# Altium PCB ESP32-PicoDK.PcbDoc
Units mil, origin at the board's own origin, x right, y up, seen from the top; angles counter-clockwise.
Board outline 2080 x 860 mil, 2 copper layers (Top1, Bottom2), stack 40.202 mil thick; 41 components, 60 nets, 226 pads, 128 vias.
Unrouted connection lines stored in the file: 56.
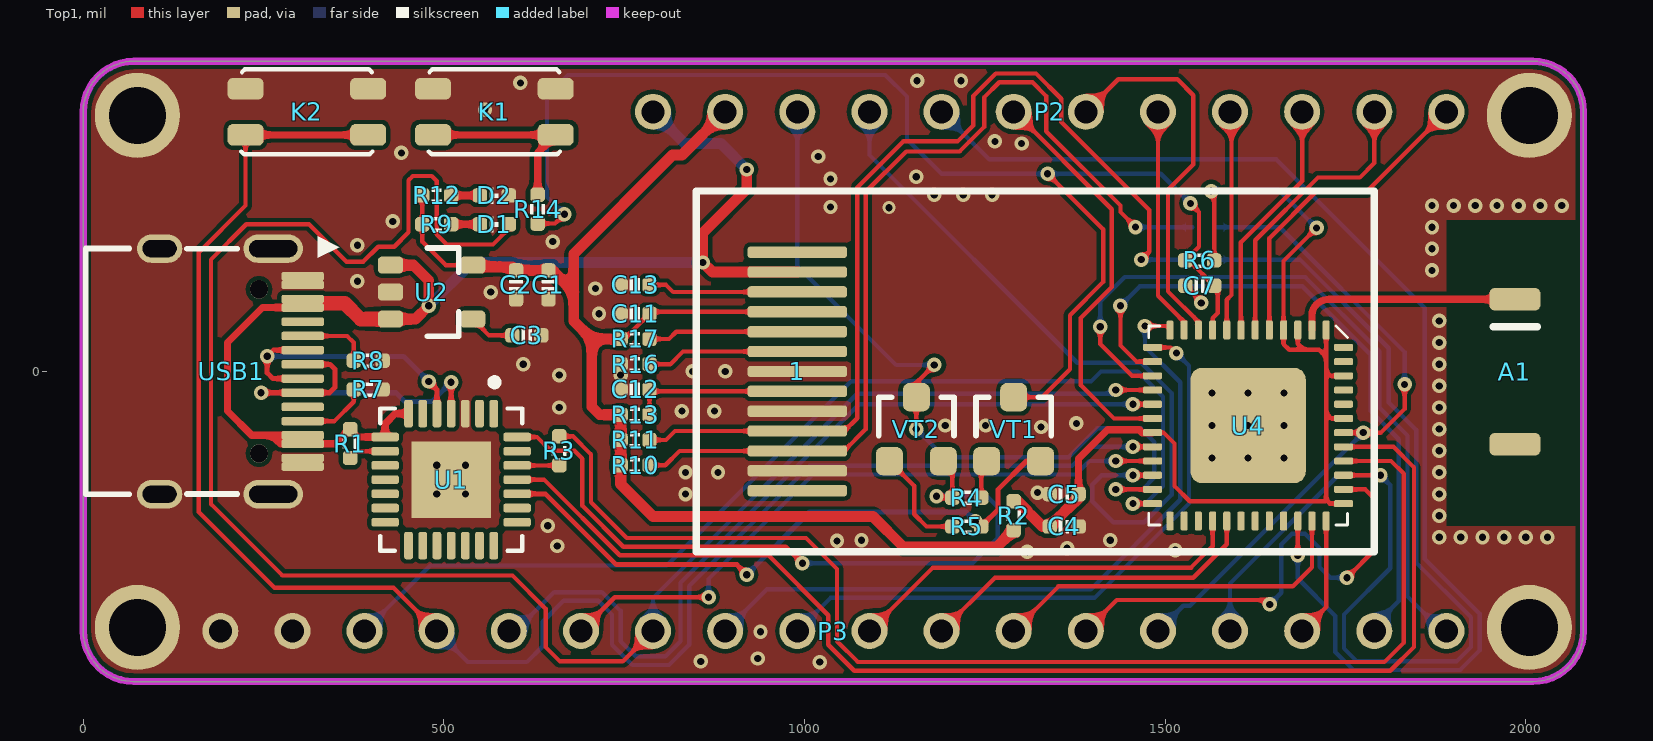
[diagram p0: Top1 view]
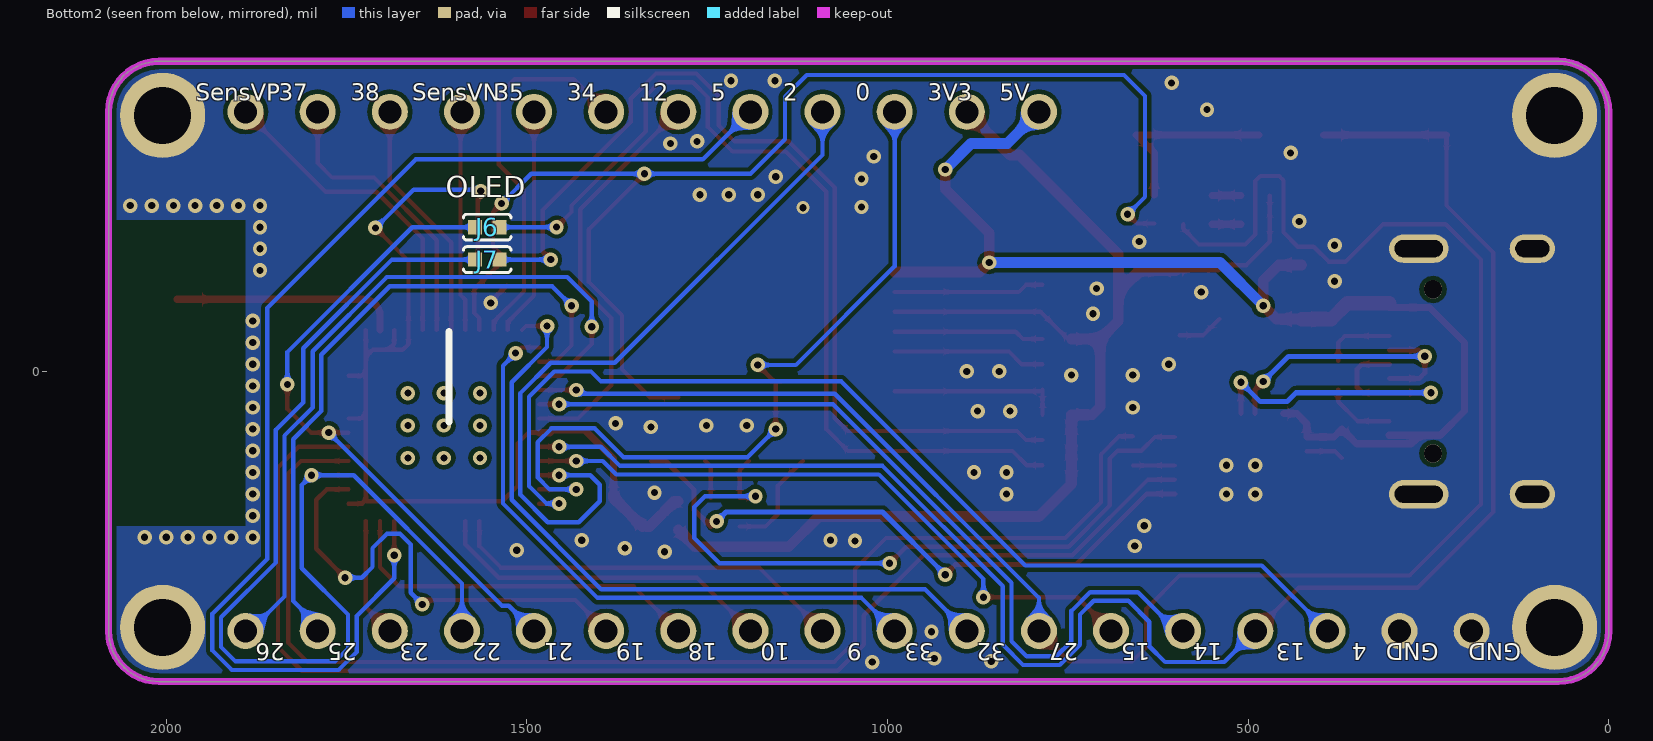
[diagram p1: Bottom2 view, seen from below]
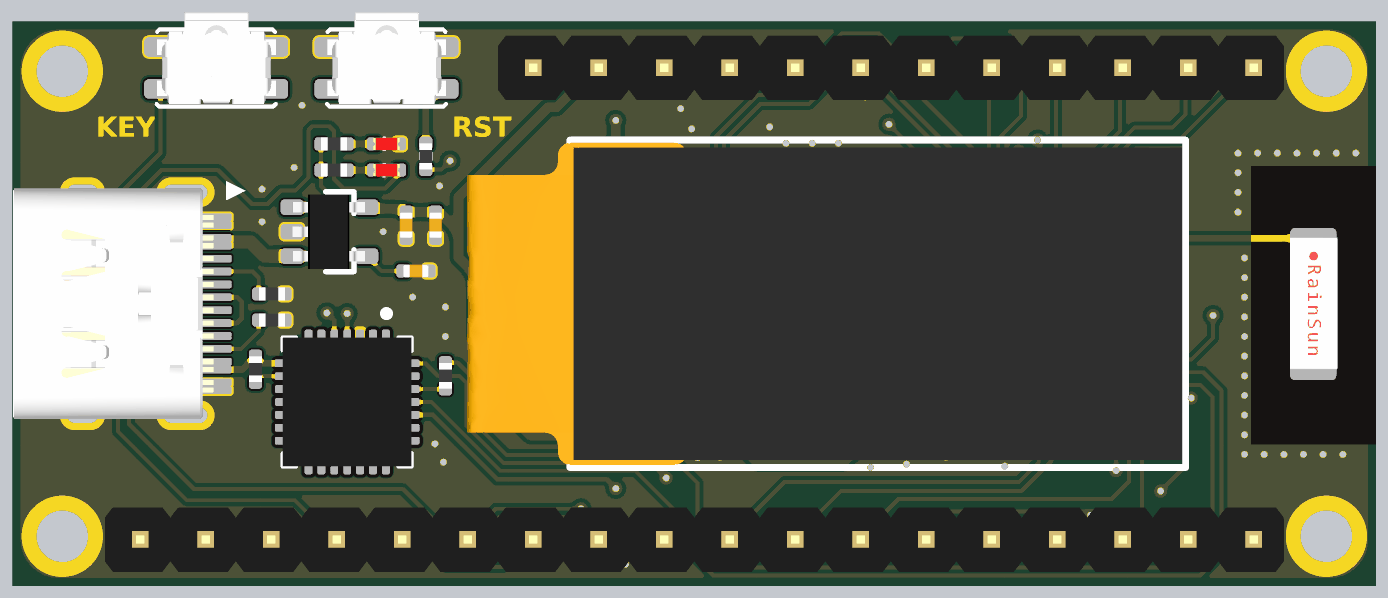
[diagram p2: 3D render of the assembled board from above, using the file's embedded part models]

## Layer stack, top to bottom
Top Solder: solder mask 0.4, Solder Resist, Dk 3.5
Top1: signal copper 1.4
Dielectric 1: core 37.4016, FR-4, Dk 4.2
Bottom2: signal copper 1.4
Bottom Solder: solder mask 0.4, Solder Resist, Dk 3.5

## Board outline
0,-360 0,360 cw(c70,360) 70,430 2010,430 cw(c2010,360) 2080,360 2080,-360 cw(c2010,-360) 2010,-430 70,-430 cw(c70,-360)

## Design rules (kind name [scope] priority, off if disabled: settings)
Clearance [All] p1: gap=6 ignorepadtopadclearanceinfootprint=FALSE
ComponentClearance [All] p1: gap=0 collisioncheckmode=3 verticalgap=0 showdistances=FALSE
DiffPairsRouting [All] p1: maxlimit=9 minlimit=9 mostfreqgap=9 toplayer_minwidth=4 toplayer_maxwidth=4 toplayer_prefwidth=4 bottomlayer_minwidth=4 bottomlayer_maxwidth=4 bottomlayer_prefwidth=4 maxuncoupledlength=500
FanoutControl Fanout_BGA [All] p1: bgadir=Out bgaviamode=Centered fanoutstyle=Auto fanoutdirection=Alternating viagrid=1 // Fanout_BGA (Default Rule)
HoleSize [All] p1: absolutevalues=TRUE maxlimit=10000 minlimit=8 maxpercent=80.000 minpercent=20.000
MinimumSolderMaskSliver [All] p1 off: minsoldermaskwidth=2
PlaneClearance [All] p1: clearance=8
PlaneConnect [All] p1: planeconnectstyle=Direct reliefexpansion=20 reliefentries=4 reliefconductorwidth=10 reliefairgap=10
PolygonConnect [All] p1: connectstyle=Direct reliefconductorwidth=10 reliefentries=4 polygonreliefangle="90 Angle" airgapwidth=10
RoutingVias [All] p1: holewidth=8 width=16 viastyle="Through Hole" minholewidth=6 minwidth=12 maxholewidth=28 maxwidth=50
SilkToBoardRegionClearance [All] p1 off:
SilkToSilkClearance [All] p1: silktosilkclearance=0
SilkToSolderMaskClearance [IsPad] p1: minsilkscreentomaskgap=0 clearancetoexposedcopper=TRUE
SolderMaskExpansion [All] p1: expansion=3
Width [All] p1: maxlimit=10000 minlimit=6 preferedwidth=7
20 further rules are at their usual default settings.

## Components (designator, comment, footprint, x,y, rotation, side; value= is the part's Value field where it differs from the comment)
1 "OLED-12880" OLED-12880 990,0 r180 top locked
A1 "RAINSUN" ANT-Rainsun-AN5120 1985,0 r270 top
C1 "0.1uF" CAP_0402 645,120 r90 top value=0.1u
C2 "10uF" CAP_0402 600,120 r90 top value=0.1u
C3 "10nF" CAP_0402 615,50 r180 top value=0.1u
C4 "10uF" CAP_0402 1360,-215 r180 top value=0.1u
C5 "0.1uF" CAP_0402 1360,-170 r0 top value=0.1u
C7 "0.1uF" CAP_0402 1548,118.89 r180 top value=0.1u
C11 "10uF" CAP_0402 765,80 r0 top value=0.1u
C12 "10uF" CAP_0402 765,-25 r0 top value=0.1u
C13 "10uF" CAP_0402 765,120 r0 top value=0.1u
D1 "color?" LED_0402_RED 570,204 r0 top
D2 "color?" LED_0402_RED 570,244 r0 top
J6 "跳线" 0402-0R 1555,200 r0 bottom
J7 "跳线" 0402-0R 1555,155 r0 bottom
K1 "TACT 4P" ButtonTACT_3.5*3.55_90 570,360 r0 top value=3.4x3.5
K2 "TACT 4P" ButtonTACT_3.5*3.55_90 310,360 r0 top value=3.4x3.5
P2 "HDR1x12_2.54" HDR1X12_2.54_180 1890,360 r270 top locked
P3 "HDR1x18_2.54" HDR1X18_2.54_180 1890,-360 r270 top locked
R1 "10K" RES_0402 370,-100 r270 top value=22R
R2 "0R" RES_0402 1290,-200 r90 top value=22R
R3 "200R" RES_0402 660,-110 r270 top value=22R
R4 "12K" RES_0402 1225,-175 r0 top value=22R
R5 "12K" RES_0402 1225,-215 r180 top value=22R
R6 "10K" RES_0402 1548,153.89 r180 top value=22R
R7 "5.1K" RES_0402 395,-25 r0 top value=22R
R8 "5.1K" RES_0402 395,15 r0 top value=22R
R9 "1K" RES_0402 490,204 r0 top value=22R
R10 "10K" RES_0402 765,-130 r180 top value=22R
R11 "10K" RES_0402 765,-95 r180 top value=22R
R12 "1K" RES_0402 490,244 r0 top value=22R
R13 "10K" RES_0402 765,-60 r180 top value=22R
R14 "1K" RES_0402 630,225 r270 top value=22R
R16 "560K" RES_0402 765,10 r180 top value=22R
R17 "4.7K" RES_0402 765,45 r180 top value=22R
U1 "CP2102" QFN-28 510,-150 r270 top value=Value
U2 "LP2992 3V3" SOT23-5 485,110 r0 top
U4 "ESP32_SIP" QFN-48_7X7 1615,-75 r270 top
USB1 "Type-C" Type-C-TOP 205,0 r180 top locked
VT1 "S8050" SMT_TRIODE_NPN 1290,-80 r0 top
VT2 "S8050" SMT_TRIODE_NPN 1155,-80 r0 top

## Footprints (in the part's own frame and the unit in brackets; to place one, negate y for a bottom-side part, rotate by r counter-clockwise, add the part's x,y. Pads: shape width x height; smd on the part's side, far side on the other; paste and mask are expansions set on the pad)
0402-0R [mm] "选择焊盘"
  rect 0.5x0.5 smd: 1(-0.432,0) 2(0.432,0)
  silkscreen extent -0.84,-0.46 0.84,0.46
ANT-Rainsun-AN5120 [mm] "选择焊盘"
  rrect50% 0.8x1.8 smd: 1(-2.54,0) ""(2.563,0)
  silkscreen extent -1.57,-0.76 -1.57,0.79, body extent -2.57,-0.91 2.54,0.94, height 1.32
ButtonTACT_3.5*3.55_90 [mil]
  rrect50% 50x30 smd: 1(-85,32) 2(-85,-32) 3(85,32) 4(85,-32)
  silkscreen extent -91,-59 91,59, body extent -90,-55 91,85, height 56
CAP_0402 [mil]
  rrect50% 20x20 smd: 1(-20,0) 2(20,0)
  silkscreen extent -7,-9 7,9, body extent -20,-10 20,10, height 20
HDR1X12_2.54_180 [mil]
  round 50 hole 32: 1(0,0) 2(0,-100) 3(0,-200) 4(0,-300) 5(0,-400) 6(0,-500) 7(0,-600) 8(0,-700) 9(0,-800) 10(0,-900) 11(0,-1000) 12(0,-1100)
  body extent -49,-1150 49,50, height 323
HDR1X18_2.54_180 [mil]
  round 50 hole 32: 1(0,0) 2(0,-100) 3(0,-200) 4(0,-300) 5(0,-400) 6(0,-500) 7(0,-600) 8(0,-700) 9(0,-800) 10(0,-900) 11(0,-1000) 12(0,-1100) 13(0,-1200) 14(0,-1300) 15(0,-1400) 16(0,-1500) 17(0,-1600) 18(0,-1700)
  body extent -49,-1750 49,50, height 323
LED_0402_RED [mil]
  rrect50% 20x20 smd: 1(-20,0) 2(20,0)
  silkscreen extent -6,-10 6,10, body extent -20,-10 20,10, height 18
OLED-12880 [mm]
  rrect50% 3.5x0.4 smd: 1(0,-4.2) 2(0,-3.5) 3(0,-2.8) 4(0,-2.1) 5(0,-1.4) 6(0,-0.7) 7(0,0) 8(0,0.7) 9(0,1.4) 10(0,2.1) 11(0,2.8) 12(0,3.5) 13(0,4.2)
  silkscreen extent -20.32,-6.35 3.56,6.35, body extent -20.18,-6.25 7.54,6.25, height 1.55
QFN-28 [mil]
  rrect50% 38x12 smd mask+5: 1(-91.5,59.06) 2(-91.5,39.37) 3(-91.5,19.69) 4(-91.5,0) 5(-91.5,-19.68) 6(-91.5,-39.37) 7(-91.5,-59.06) 15(91.5,-59.06) 16(91.5,-39.37) 17(91.5,-19.68) 18(91.5,0) 19(91.5,19.69) 20(91.5,39.37) 21(91.5,59.06)
  rrect50% 12x38 smd mask+5: 8(-59.06,-91.5) 9(-39.37,-91.5) 10(-19.69,-91.5) 11(0,-91.5) 12(19.68,-91.5) 13(39.37,-91.5) 14(59.06,-91.5) 22(59.06,91.5) 23(39.37,91.5) 24(19.68,91.5) 25(0,91.5) 26(-19.69,91.5) 27(-39.37,91.5) 28(-59.06,91.5)
  rect 106.3x110.24 smd: 29(0,0)
  silkscreen extent -140,-99 99,99, body extent -99,-99 98,98, height 35
QFN-48_7X7 [mm]
  rrect50% 0.675x0.25 smd: 1(-3.363,2.75) 2(-3.363,2.25) 3(-3.363,1.75) 4(-3.363,1.25) 5(-3.363,0.75) 6(-3.363,0.25) 7(-3.363,-0.25) 8(-3.363,-0.75) 9(-3.363,-1.25) 10(-3.363,-1.75) 11(-3.363,-2.25) 12(-3.363,-2.75) 25(3.363,-2.75) 26(3.363,-2.25) 27(3.363,-1.75) 28(3.363,-1.25) 29(3.363,-0.75) 30(3.363,-0.25) 31(3.363,0.25) 32(3.363,0.75) 33(3.363,1.25) 34(3.363,1.75) 35(3.363,2.25) 36(3.363,2.75)
  rrect50% 0.25x0.675 smd: 13(-2.75,-3.363) 14(-2.25,-3.363) 15(-1.75,-3.363) 16(-1.25,-3.363) 17(-0.75,-3.363) 18(-0.25,-3.363) 19(0.25,-3.363) 20(0.75,-3.363) 21(1.25,-3.363) 22(1.75,-3.363) 23(2.25,-3.363) 24(2.75,-3.363) 37(2.75,3.363) 38(2.25,3.363) 39(1.75,3.363) 40(1.25,3.363) 41(0.75,3.363) 42(0.25,3.363) 43(-0.25,3.363) 44(-0.75,3.363) 45(-1.25,3.363) 46(-1.75,3.363) 47(-2.25,3.363) 48(-2.75,3.363)
  rrect20% 4.064x4.064 smd: 49(0,0)
  silkscreen extent -3.5,-3.5 3.5,3.5, body extent -3.5,-3.5 3.5,3.5, height 1
RES_0402 [mil]
  rrect50% 20x20 smd: 1(-20,0) 2(20,0)
  silkscreen extent -7,-10 7,10, body extent -20,-10 20,10, height 14
SMT_TRIODE_NPN [mm] "Surface mount NPN transistor, package SOT-23"
  rrect50% 0.95x1 smd: 1(-0.95,-1.125) 2(0.95,-1.125) 3(0,1.125)
  silkscreen extent -1.33,-0.22 1.32,1.13, body extent -1.45,-1.4 1.45,1.4, height 1.3
SOT23-5 [mm] "SOT23, 3-Leads, Body 3.1x3.0mm (max), Pitch 0.95mm, IPC Medium Density"
  rrect50% 0.889x0.6 smd: 1(-1.5,0.95) 2(-1.5,0) 3(-1.5,-0.95) 4(1.396,-0.95) 5(1.396,0.95)
  silkscreen extent -0.2,-1.55 0.9,1.55, body extent -1.48,-1.45 1.32,1.45, height 1.2
Type-C-TOP [mm]
  round 0.65 hole 0.65: 0(-0.98,2.89) 0(-0.98,-2.89)
  oval 1.6x1 hole 0.6 slot 1.2 at 0 deg: 1(2.52,4.325) 2(2.52,-4.325)
  oval 2.1x1 hole 0.6 slot 1.7 at 0 deg: 3(-1.48,-4.325) 4(-1.48,4.325)
  rrect50% 1.5x0.3 smd: A1(-2.52,-3.35) A4(-2.52,-2.55) A5(-2.52,-1.25) A6(-2.52,-0.25) A7(-2.52,0.25) A8(-2.52,1.25) A9(-2.52,2.55) A12(-2.52,3.35) B1(-2.52,3.05) B4(-2.52,2.25) B5(-2.52,1.75) B6(-2.52,0.75) B7(-2.52,-0.75) B8(-2.52,-1.75) B9(-2.52,-2.25) B12(-2.52,-3.05)
  silkscreen extent -0.22,-4.33 5.12,4.33, body extent -2.57,-4.48 5.18,4.48, height 3.26

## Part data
A1: library part ANT-Rainsun-AP5120
C1 C2 C3 C4 C5 C7 C11 C12 C13: library part 电容-0402, "Capacitor"
D1 D2: library part LED_0402, "LED"
J6 J7: "Resistor"
K1 K2: library part ButtonTACT, "Button"
P2 P3: "Header"
R1 R2 R3 R4 R5 R6 R7 R8 R9 R10 R11 R12 R13 R14 R16 R17: library part 电阻-0402, "Resistor"
U1: "USBתTTL"
U2: library part LP2992, "LDO"
U4: library part ESP32-PICO
USB1: library part USB-Type-C-TOP
VT1 VT2: library part SMT_TRIODE_NPN, "Surface mount NPN transistor, package SOT-23"

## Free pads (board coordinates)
  round 118.11 hole 78.74: ""(75,-355) ""(75,355) ""(2005,-355) ""(2005,355)

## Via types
v1: diameter 20, hole 10, Top1 to Bottom2, tented both sides, 127 vias
v2: diameter 18, hole 10, Top1 to Bottom2, tented both sides, 1 vias

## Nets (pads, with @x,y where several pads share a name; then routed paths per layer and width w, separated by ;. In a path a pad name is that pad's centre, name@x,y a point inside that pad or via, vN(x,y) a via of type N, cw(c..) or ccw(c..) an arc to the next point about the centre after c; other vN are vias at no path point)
3V3A: C4.2 C5.2 R2.2 R6.1 U4.1 U4.3 U4.4 U4.19 U4.37 U4.43 U4.46 | length 1465.8
  Top1 w6: U4.19 1497.84,-84.84 1513,-100 1513,-159 1534,-180 1721.54,-180 1723.27,-178.27 ; v1(1563.99,250) 1568,245.99 R6.1 ; U4.3 1683.9,38.74 1692.63,30 ; v1(1710,199) 1664.21,153.21 U4.4 1664.21,37.79 1672,30 1692.63,30 ; U4.1 1723.27,20 ; U4.37 1728.27,-183.27 1723.27,-178.27 ; U4.43 1730.16,-65.16 1723.27,-58.27 ; U4.46 1729.1,-6.1 1723.27,-0.27 ; 1692.63,30 1713.27,30 1723.27,20 ; 1723.27,-178.27 1723.27,-58.27 ; 1723.27,-58.27 1723.27,-0.27 ; 1723.27,-0.27 1723.27,20
  Top1 w10: C5.2 1380,-121 1420,-81 1464,-81 1468,-85 1482.46,-85 U4.19
  Top1 w15: R2.2 1295,-180 1330,-215 C4.2@1335,-215 ; C4.2 1380,-175 C5.2
  Bottom2 w6: v1(1563.99,250) 1565.99,252 1657,252 v1(1710,199)
CP_Rx: U1.25 U4.41 | length 1749.4
  Top1 w6: U1.25 638.68,-150 743.68,-255 950,-255 1033,-338 1033,-379 1069,-415 1812,-415 1845,-382 1845,-133 1816.53,-104.53 U4.41
CP_Tx: R3.1 U4.40 | length 1734.3
  Top1 w6: R3.1 679,-90 704,-115 704,-181.38 753.62,-231 1002,-231 1045,-274 1045,-374.03 1073.97,-403 1804,-403 1831,-376 1831,-142 1813.21,-124.21 U4.40
DTR: R4.1 U1.28 VT2.2 | length 1004.8
  Top1 w6: U1.28 628.95,-90.94 648,-110 681,-110 692,-121 692,-186.35 748.65,-243 974,-243 v1(997,-266) ; v1(1183,-173) 1185,-175 R4.1 1205,-136.89 VT2.2
  Bottom2 w6: v1(997,-266) 1233,-266 1268,-231 1268,-188 1253,-173 v1(1183,-173)
EN: C7.1 R6.2 R14.2 U4.9 VT1.3 | length 1857.6
  Top1 w6: R14.2 654,205 v1(667,218) ; VT1.3 1329.29,-35.71 1368,3 1368,78 1414,124 1414,197 v1(1337,274) ; v1(1535,233) 1547,221 1547,172.89 R6.2 1533,153.89 C7.1 1573,113.89 1573,81 1565.79,73.79 U4.9
  Bottom2 w6: v1(667,218) 643,242 643,382 672,411 1112,411 1142,381 1142,322 1190,274 v1(1337,274) 1494,274 v1(1535,233)
FLASH_CLK: U4.31
FLASH_CS: U4.25
FLASH_SD0: U4.27
FLASH_SD1: U4.33
FLASH_SD2: U4.30
FLASH_SD3: U4.32
GND: 1.7 1.9 1.12 C1.1 C2.1 C3.1 C4.1 C5.1 C7.2 C11.1 C12.1 C13.1 D2.2 K1.1 K1.3 K2.1 K2.3 P3.17 P3.18 pad. R7.2 R8.2 R16.2 U1.3 U1.29 U2.2 USB1.1 USB1.2 USB1.3 USB1.4 USB1.A1 USB1.A12 USB1.B1 USB1.B12 | length 33
  Top1 w6: C7.2 1550,96.89 v1(1550,95)
  other v1: 1021,-403 856,-402 935,-398 939,-361 1309,-250 1514,-248 1364,-245 657,-242 1045,-235 1079,-234 1424,-234 1880,-230 1910,-230 1940,-230 1970,-230 2000,-230 2030,-230 644,-214 1880,-200 490,-170 530,-170 835,-170 1880,-170 1323,-168 835,-140 880,-140 1880,-140 490,-130 530,-130 1880,-110 1880,-80 1328,-77 1195,-75 1251,-75 1377,-72 830,-55 875,-55 660,-50 1880,-50 1880,-20 660,-5 745,-5 845,0 890,0 610,10 1880,10 1880,40 1880,70 715,80 565,110 710,115 380,125 1870,140 1870,170 380,175 651,180 1870,200 429,208 1036,228 1870,230 1900,230 1930,230 1960,230 1990,230 2020,230 2050,230 1180,245 1220,245 1260,245 1036,267 1155,270 1019,298 441,303 1301,316 1264,319 557,363 606,400 1156,403 1217,403
  other v2: 1117,227
GPIO0: P2.10 U4.23 VT2.3 | length 1091.3
  Top1 w6: v1(1155,-80) VT2.3 1155,-16 v1(1180,9) ; v1(1431.42,-163.58) U4.23
  Bottom2 w6: P2.10 990,146 1127,9 v1(1180,9) ; v1(1155,-80) 1194,-119 1366,-119 1406,-79 1466,-79 1485,-98 1485,-147 1468.42,-163.58 v1(1431.42,-163.58)
GPIO2: P2.9 U4.22 | length 1006.5
  Top1 w6: v1(1455.27,-143.9) U4.22
  Bottom2 w6: P2.9 1090,300 1378,12 1457,12 1466.97,12 1509,-30.03 1509,-171 1471,-209 1428,-209 1399,-180 1399,-157 1412.1,-143.9 v1(1455.27,-143.9)
GPIO4: P3.16 U4.24 | length 1473.7
  Top1 w6: v1(1455.27,-183.27) U4.24
  Bottom2 w6: P3.16 481,-269 809,-269 1064.21,-13.79 1397.21,-13.79 1411,0 1462,0 1497,-35 1497,-159 1472.73,-183.27 v1(1455.27,-183.27)
GPIO5: P2.8 U4.34 | length 1713.9
  Top1 w6: v1(1683.9,-254.9) U4.34
  Bottom2 w6: P2.8 1256,294 1654,294 1860,88 1860,-260 1936,-336 1936,-386.97 1908.97,-414 1761.03,-414 1736,-388.97 1736,-339 1683.9,-286.9 v1(1683.9,-254.9)
GPIO9: P3.9 U4.28 | length 559.4
  Top1 w6: P3.9 1178,-272 1536.03,-272 1565.79,-242.24 U4.28
GPIO10: P3.8 U4.29 | length 477.5
  Top1 w6: P3.8 1264,-286 1539,-286 1585.47,-239.53 U4.29
GPIO12: P2.7 U4.18 | length 572.5
  Top1 w6: P2.7 1291,360 1426,225 1426,117 1383,74 1383,-19 1429.16,-65.16 U4.18
GPIO13: K2.2 K2.4 P3.15 U4.20 | length 2418.1
  Top1 w6: K2.2 225,230 160,165 160,-195 265,-300 430,-300 P3.15 ; v1(1455.27,-104.53) U4.20
  Top1 w10: K2.2 K2.4
  Bottom2 w6: P3.15 533,-403 615,-403 637,-381 637,-347 666,-318 714,-318 733,-337 733,-378.97 761.03,-407 812.03,-407 840,-379.03 840,-297.91 1006.91,-131 1370.97,-131 1397.44,-104.53 v1(1455.27,-104.53)
GPIO14: P3.14 U4.17 | length 1168.7
  Top1 w6: v1(1455.27,-45.47) U4.17
  Bottom2 w6: P3.14 599,-360 653,-306 718.97,-306 745,-332.03 745,-342 745,-374 766,-395 807.06,-395 828,-374.06 828,-292.94 1075.47,-45.47 v1(1455.27,-45.47)
GPIO15: P3.13 U4.21 | length 905
  Top1 w6: P3.13 737,-313 v1(867,-313) ; v1(1431.42,-124.21) U4.21
  Bottom2 w6: v1(867,-313) 867,-287.88 1011.88,-143 1375.94,-143 1394.73,-124.21 v1(1431.42,-124.21)
GPIO18: P3.7 U4.35 | length 514.3
  Top1 w6: P3.7 1352,-298 1677,-298 1703.58,-271.42 U4.35
GPIO19: P3.6 U4.38 | length 677.8
  Top1 w6: P3.6 1433,-317 1639,-317 v1(1645,-323) ; U4.38 1777.58,-163.58 1792,-178 1792,-246 v1(1752,-286)
  Bottom2 w6: v1(1645,-323) 1661,-307 1661,-239.97 1675.97,-225 1694,-225 1714,-245 1714,-271 1729,-286 v1(1752,-286)
GPIO21: J6.2 P3.5 U4.42 | length 907.6
  Top1 w6: U4.42 v1(1774.73,-84.84) 1799.16,-84.84 1832,-52 v1(1832,-18)
  Bottom2 w6: P3.5 1525,-325 1534.57,-325 v1(1774.73,-84.84) ; J6.2 1659,200 1832,27 v1(1832,-18)
GPIO22: J7.2 P3.4 U4.39 | length 1602.1
  Top1 w6: U4.39 v1(1798.58,-143.9)
  Bottom2 w6: J7.2 1687.03,155 1810,32.03 1810,-43 1848,-81 1848,-264.97 1924,-340.97 1924,-382 1904,-402 1766,-402 1748,-384 1748,-337 1812,-273 1812,-157.35 v1@1798.58,-143.93 ; P3.4 1590,-294 1740.1,-143.9 v1(1798.58,-143.9)
GPIO23: P3.3 U4.36 | length 166.4
  Top1 w6: P3.3 1723.27,-326.73 U4.36
GPIO25: P3.2 U4.14 | length 919.8
  Top1 w6: v1(1438,91) 1438,35.91 1460.33,13.58 U4.14
  Bottom2 w6: v1(1438,91) 1465,118 1690.09,118 1785,23.09 1785,-54.97 1824,-93.97 1824,-318.33 1790,-352.33 P3.2
GPIO26: P3.1 U4.15 | length 1023.7
  Top1 w6: v1(1410.03,62.03) 1410,38 1454.1,-6.1 U4.15
  Bottom2 w6: v1(1410.03,62.03) 1410,97 1444,131 1694.06,131 1797,28.06 1797,-50 1836,-89 1836,-312 1884,-360 P3.1
GPIO27: D1.2 P3.12 U4.16 | length 2592.9
  Top1 w6: D1.2 590,198 568,176 504,176 490,190 490,264 483,271 457,271 451,265 451,193 431,173 409,173 388,152 365,152 313,204 226,204 177,155 177,-184 276,-283 595,-283 641,-329 641,-382 661,-402 748,-402 P3.12 ; v1(1431.42,-25.79) U4.16
  Bottom2 w6: P3.12 790,-313.97 1072.97,-31 1426.2,-31 v1(1431.42,-25.79)
GPIO32: P3.11 U4.12 | length 1004.8
  Top1 w6: v1(1472,63) 1501.11,63 U4.12
  Bottom2 w6: P3.11 948,-302 1397.03,-302 1521,-178.03 1521,-15.03 1472,33.97 v1(1472,63)
GPIO33: P3.10 U4.13 | length 868.2
  Top1 w6: U4.13 1507.73,33.27 v1(1515.58,25.42)
  Bottom2 w6: P3.10 1036,-314 1402,-314 1533,-183 1533,8 v1(1515.58,25.42)
GPIO34: P2.6 U4.10 | length 534.3
  Top1 w6: P2.6 1435,405 1517,405 1539,383 1539,287 1504,252 1504,111 1546.1,68.9 U4.10
GPIO35: P2.5 U4.11 | length 317.7
  Top1 w6: P2.5 1490,105 1526.42,68.58 U4.11
GPIO37: P2.2 U4.6 | length 405
  Top1 w6: U4.6 1624.84,181.87 1711.97,269 1770,269 1790,289 P2.2
GPIO38: P2.3 U4.7 | length 337.9
  Top1 w6: U4.7 1605,57.54 1605,179 1690,264 P2.3
Net1_3: 1.3 C13.2 | length 209
  Top1 w6: C13.2 808,120 817.76,110.24 1.3
Net1_5: 1.5 R17.1 | length 209.2
  Top1 w6: R17.1 812,45 822.12,55.12 1.5
Net1_6: 1.6 R16.1 | length 212.3
  Top1 w6: R16.1 814,10 831.56,27.56 1.6
Net1_8: 1.8 C12.2 R13.1 | length 237.4
  Top1 w6: R13.1 C12.2 ; C12.2@787.56,-27.56 1.8
NetA1_1: A1.1 U4.2 | length 314.2
  Top1 w10: U4.2 1703.58,78.09 cw(c1723.96,78.09) 1709.55,92.5 cw(c1727.66,74.39) 1727.66,100 A1.1
NetC3_2: C3.2 U2.4 | length 64.4
  Top1 w6: U2.4 562.54,50 C3.2
NetD1_1: D1.1 R9.2 | length 40
  Top1 w10: R9.2 D1.1
NetD2_1: D2.1 R12.2 | length 40
  Top1 w10: R12.2 D2.1
NetK1_2: K1.2 K1.4 R14.1 | length 263.4
  Top1 w10: K1.2 K1.4 630,303 R14.1
NetR1_2: R1.2 U1.9 | length 52.4
  Top1 w6: R1.2 379.37,-110.63 U1.9
NetR3_2: R3.2 U1.26 | length 58.2
  Top1 w6: U1.26 R3.2@659.69,-130.31
NetR4_2: R4.2 VT1.1 | length 53.9
  Top1 w6: R4.2 1245,-131.89 VT1.1
NetR5_2: R5.2 VT2.1 | length 148
  Top1 w6: VT2.1 1152,-158.69 1152,-198 1169,-215 R5.2
NetR7_1: R7.1 USB1.B5 | length 98.9
  Top1 w6: USB1.B5 348.1,-68.9 375,-42 R7.1
NetR8_1: R8.1 USB1.A5 | length 99.6
  Top1 w6: USB1.A5 365.79,49.21 375,40 R8.1
OLED_SCL: 1.10 J7.1 R11.1 | length 1356.5
  Top1 w6: R11.1 808,-95 820.33,-82.67 1.10 1055.33,-82.67 1073,-65 1073,255 1137,319 1212.03,319 1234,340.97 1234,382 1265,413 1320.97,413 1356,377.97 1356,345.92 1478,223.92 1478,166 v1(1467,155)
  Bottom2 w6: v1(1467,155) J7.1
OLED_SDA: 1.11 J6.1 R10.1 | length 1306.9
  Top1 w6: R10.1 807,-130 826.77,-110.23 1.11 1054.77,-110.23 1085,-80 1085,249 1141,305 1215,305 1249,339 1249,380 1270,401 1316,401 1335,382 1335,333 1438,230 1438,221 v1(1458.88,200.12)
  Bottom2 w6: v1(1458.88,200.12) 1459,200 J6.1
RTS: R5.1 U1.24 VT1.2 | length 859.8
  Top1 w7: U1.24 640.69,-169.68 739,-268 906,-268 v1(920,-282) ; R5.1 1268,-192 1268,-164 1307.71,-124.29 VT1.2
  Bottom2 w7: v1(920,-282) 1007,-195 1224,-195 v1(1237,-208)
SENSOR_VN: P2.4 U4.8 | length 306.2
  Top1 w6: U4.8 1585.47,99.44 1592,105.97 1592,358 P2.4
SENSOR_VP: P2.1 U4.5 | length 445.3
  Top1 w6: U4.5 1644.53,184.59 1708.94,249 1779,249 P2.1
USB-PWR-DM: U1.5 USB1.A7 USB1.B7 | length 415.9
  Top1 w7: USB1.A7 262.84,-9.84 255,-2 v1(255,21) 263.53,29.53 USB1.B7 ; v1(479,-14) 490.32,-25.31 U1.5
  Bottom2 w7: v1(255,21) 444,21 v1(479,-14)
USB-PWR-DP: U1.4 USB1.A6 USB1.B6 | length 501.5
  Top1 w7: v1(246.53,-29.53) USB1.B6 341.47,-29.53 349,-22 349,3 342.16,9.84 USB1.A6 ; U1.4 v1(510,-15)
  Bottom2 w7: v1(246.53,-29.53) 433.53,-29.53 445.91,-41.91 483.09,-41.91 v1(510,-15)
VBUS: 1.2 P2.12 R1.1 U1.7 U1.8 U2.1 U2.3 USB1.A4 USB1.A9 USB1.B4 USB1.B9 | length 1715.7
  Top1 w10: USB1.B4 262,-88.58 ; USB1.B9 248.58,88.58 200,40 200,-55 233.58,-88.58 262,-88.58 ; U1.7 432.5,-58.5 418.5,-72.5 U1.8 380.94,-90.94 R1.1 349.61,-100.39 USB1.A9 273.81,-100.39 262,-88.58
  Top1 w15: U2.3 460.6,72.6 v1(479,91) 479,126 457.6,147.4 U2.1 ; v1(920,280) 920,253 859,192 v1(859,151) 872.2,137.8 1.2
  Top1 w20: USB1.A4@304.21,94.58 362.42,94.58 384.4,72.6 U2.3
  Bottom2 w15: v1(479,91) 539,151 v1(859,151) ; P2.12 834,316 884,316 v1(920,280)
VCC_3V3: 1.4 C1.2 C2.2 C11.2 P2.11 R2.1 R9.1 R10.2 R11.2 R12.1 R13.2 R17.2 U2.5 | length 1848.7
  Top1 w6: R12.1 R9.1 470,180 502.6,147.4 U2.5 ; R17.2 750,45 C11.2 787.68,82.68 1.4
  Top1 w15: U2.5 542.35,145 595,145 C2.2 C1.2 650,140 680,110 ; R17.2 705,45 ; P2.11 830,300 817,300 680,163 680,110 ; R2.1 1267,-243 1137,-243 1095,-201 1062,-201 790,-201 745,-156 R10.2 R11.2 R13.2 716,-60 705,-49 705,45 ; 680,110 680,70 705,45
pads on no net: 1.1 1.13 A1. U1.1 U1.2 U1.6 U1.10 U1.11 U1.12 U1.13 U1.14 U1.15 U1.16 U1.17 U1.18 U1.19 U1.20 U1.21 U1.22 U1.23 U1.27 U4.26 U4.44 U4.45 U4.47 U4.48 U4.49 USB1.0 USB1.A8 USB1.B8
copper on no net:
  other v1: 1565,-120 1615,-120 1665,-120 1565,-75 1615,-75 1665,-75 1565,-30 1615,-30 1665,-30

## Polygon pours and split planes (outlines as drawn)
GND on Top1 "GND_L01_P000" (solid, remove dead copper, pour order 0): -20,460 -20,-460 2100,-460 2100,460
GND on Bottom2 "GND_L02_P001" (solid, remove dead copper, pour order 1): -20,460 -20,-460 2100,-460 2100,460

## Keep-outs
Keep-Out Layer:
  the board outline again, w10

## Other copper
Top1:
  pour cut-out: 1890,210 1890,-215 2115,-215 2115,210
Bottom2:
  pour cut-out: 1890,210 1890,-215 2115,-215 2115,210

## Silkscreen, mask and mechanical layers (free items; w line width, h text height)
Top Overlay:
  region: 325,157.5 325,187.5 355,172.5
Bottom Overlay:
  lines w10: 1607.84,-69.84 1607.84,55.16
  text "5V" at 844.24,367.98 h40
  text "3V3" at 944.24,367.98 h40
  text "0" at 1044.24,367.98 h40
  text "2" at 1144.24,367.98 h40
  text "5" at 1244.24,367.98 h40
  text "12" at 1344.24,367.98 h40
  text "34" at 1444.24,367.98 h40
  text "35" at 1544.24,367.98 h40
  text "SensVN" at 1659.09,367.98 h40
  text "38" at 1744.24,367.98 h40
  text "37" at 1844.24,367.98 h40
  text "SensVP" at 1959.09,367.98 h40
  text "OLED" at 1612.58,232.01 h50
  text "GND" at 120.91,-368.98 h40 r180
  text "GND" at 235.76,-368.98 h40 r180
  text "4" at 335.76,-368.98 h40 r180
  text "13" at 420.91,-368.98 h40 r180
  text "14" at 535.76,-368.98 h40 r180
  text "15" at 635.76,-368.98 h40 r180
  text "27" at 735.76,-368.98 h40 r180
  text "32" at 835.76,-368.98 h40 r180
  text "33" at 935.76,-368.98 h40 r180
  text "9" at 1035.76,-368.98 h40 r180
  text "10" at 1135.76,-368.98 h40 r180
  text "18" at 1235.76,-368.98 h40 r180
  text "19" at 1335.76,-368.98 h40 r180
  text "21" at 1435.76,-368.98 h40 r180
  text "22" at 1535.76,-368.98 h40 r180
  text "23" at 1635.76,-368.98 h40 r180
  text "25" at 1735.76,-368.98 h40 r180
  text "26" at 1835.76,-368.98 h40 r180
Top Solder:
  rectangle: 1890,-215 2115,210
  text "KEY" at 118.18,236.99 h60
  text "RST" at 661.65,236.99 h60
Bottom Solder:
  rectangle: 1890,-215 2115,210
Mechanical 1:
  the board outline again, w10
